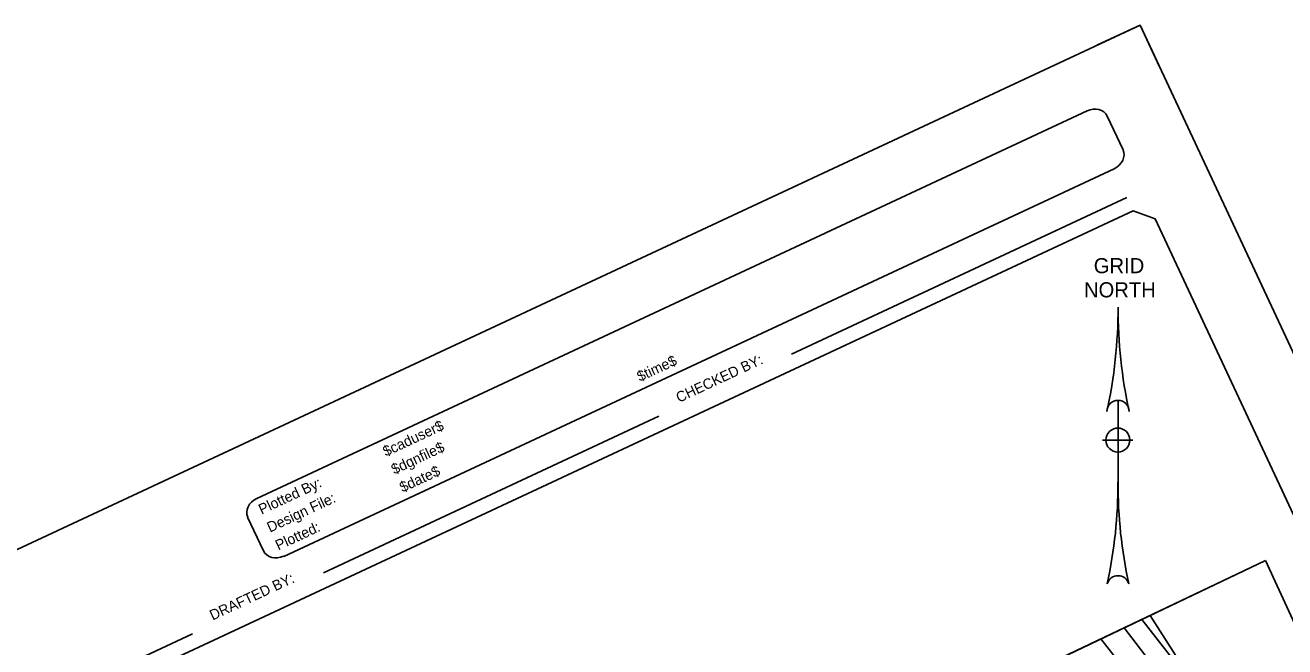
# Model space of a CAD drawing. Extents: x 1040567 to 1041254, y 1126791 to 1127594.
# Drawn here: x 1040797.5 to 1040987.8, y 1127499.7 to 1127593.6 of the extents above; entities that cross this region are included whole.
import ezdxf

# ---------------------------------------------------------------- set-up
doc = ezdxf.new("R2010")
doc.units = 0
for name, color, linetype in [('clip boundary', 7, 'Continuous'), ('DELB', 7, 'Continuous'), ('MHB', 7, 'Continuous'), ('NBS_P', 7, 'Continuous'), ('NBS_P_T', 7, 'Continuous'), ('NML_P', 7, 'Continuous'), ('NNA_P', 7, 'Continuous'), ('SHEET_BORDER', 7, 'Continuous'), ('SHEET_BORDER_CUT', 7, 'Continuous'), ('SHEET_BORDER_TEXT', 7, 'Continuous')]:
    doc.layers.add(name, color=color, linetype=linetype)

msp = doc.modelspace()

# ---------------------------------------------------------------- linework, layer by layer
at = {"layer": 'clip boundary'}
for points in [[(1040965.89, 1127593.65), (1041253.68, 1126977.55), (1040855.03, 1126791.33), (1040567.24, 1127407.43)], [(1040984.84, 1127512.73), (1041214.88, 1127013.05), (1040933.62, 1126879.17), (1040829.04, 1127018.95), (1040710.75, 1127268.88), (1040738.34, 1127281.77), (1040695.57, 1127374.92)]]:
    msp.add_lwpolyline(points, close=True, dxfattribs=at)
at = {"layer": 'DELB'}
for points in [[(1041058.7, 1127320.42), (1041045.83, 1127357.25), (1041019.86, 1127415.53), (1040987.53, 1127471.18), (1040963.49, 1127502.56)], [(1041061.69, 1127320.35), (1041047.64, 1127357.94), (1041023.1, 1127415.85), (1040990.27, 1127472.94), (1040966.17, 1127503.84)], [(1040959.96, 1127500.88), (1040984.81, 1127469.12), (1041015.12, 1127422.04), (1041038.53, 1127369.64), (1041050.29, 1127335.97), (1041054.5, 1127318.26)]]:
    msp.add_lwpolyline(points, dxfattribs=at)
at = {"layer": 'MHB'}
msp.add_lwpolyline([(1040967.39, 1127504.42), (1041043.62, 1127385.06)], dxfattribs=at)
at = {"layer": 'NBS_P'}
for p, q in [((1040957.88, 1127580.71), (1040832.44, 1127522.11)), ((1040963.31, 1127574.79), (1040960.92, 1127579.92)), ((1040836.53, 1127513.35), (1040961.97, 1127571.95)), ((1040831.07, 1127519.27), (1040833.45, 1127514.18))]:
    msp.add_line(p, q, dxfattribs=at)
for centre, major_axis, start_param, end_param in [((1040958.72, 1127578.9), (2.19, 1.02), 0, 1.570796), ((1040961.12, 1127573.76), (2.19, 1.02), 4.712389, 6.283185), ((1040833.28, 1127520.3), (-2.19, -1.02), 4.712389, 6.283185), ((1040835.66, 1127515.21), (-2.19, -1.02), 0, 1.570796)]:
    msp.add_ellipse(centre, major_axis=major_axis, ratio=0.825959, start_param=start_param, end_param=end_param, dxfattribs=at)
at = {"layer": 'NML_P'}
msp.add_line((1040710.81, 1127382.18), (1040984.84, 1127512.73), dxfattribs=at)
at = {"layer": 'NNA_P'}
for p, q in [((1040962.56, 1127524.57), (1040962.56, 1127536.94)), ((1040960.23, 1127530.92), (1040964.77, 1127530.92))]:
    msp.add_line(p, q, dxfattribs=at)
msp.add_circle((1040962.54, 1127530.94), 1.81, dxfattribs=at)
for centre, radius, start, end in [((1040889.47, 1127550.88), 73.09, 347.6515, 0.1139), ((1041035.65, 1127550.88), 73.09, 179.8844, 192.3468), ((1040962.56, 1127535.25), 1.69, 359.9991, 179.9991), ((1040889.47, 1127524.55), 73.09, 347.8917, 0.0159), ((1041035.64, 1127524.55), 73.09, 179.9824, 192.1066), ((1040962.56, 1127508.75), 1.69, 15.894, 164.1052)]:
    msp.add_arc(centre, radius, start, end, dxfattribs=at)
at = {"layer": 'SHEET_BORDER'}
for p, q in [((1040913.25, 1127543.93), (1040963.91, 1127567.6)), ((1040842.53, 1127510.89), (1040893.19, 1127534.56)), ((1040772.08, 1127477.98), (1040822.74, 1127501.65))]:
    msp.add_line(p, q, dxfattribs=at)
msp.add_lwpolyline([(1040856.06, 1126819.41), (1040852.74, 1126820.61), (1040588.22, 1127386.88), (1040589.43, 1127390.2), (1040964.86, 1127565.58), (1040968.18, 1127564.37), (1041232.7, 1126998.11), (1041231.49, 1126994.78)], close=True, dxfattribs=at)
at = {"layer": 'SHEET_BORDER_CUT'}
msp.add_lwpolyline([(1040567.24, 1127407.43), (1040855.03, 1126791.33), (1041253.68, 1126977.55), (1040965.89, 1127593.65)], close=True, dxfattribs=at)
msp.add_lwpolyline([(1040959.48, 1127590.66), (1040965.89, 1127593.65), (1040968.88, 1127587.24)], dxfattribs=at)

# ---------------------------------------------------------------- texts
at = {"layer": 'NBS_P_T'}
for s, height, p in [('$time$', 1.576, (1040890.34, 1127539.73)), ('$caduser$', 1.576, (1040851.95, 1127528.41)), ('$dgnfile$', 1.576, (1040853.22, 1127525.7)), ('$date$', 1.576, (1040854.48, 1127522.99)), ('Plotted By:', 1.5759, (1040833.17, 1127519.64)), ('Design File:', 1.5759, (1040834.44, 1127516.93)), ('Plotted:', 1.576, (1040835.71, 1127514.22))]:
    msp.add_text(s, height=height, rotation=25.0392, dxfattribs=at).set_placement(p)
at = {"layer": 'NNA_P'}
for s, p in [('GRID', (1040958.89, 1127556.16)), ('NORTH', (1040957.41, 1127552.51))]:
    msp.add_text(s, height=2.283, rotation=359.9991, dxfattribs=at).set_placement(p)
at = {"layer": 'SHEET_BORDER_TEXT'}
for s, p in [('CHECKED BY:', (1040896.24, 1127536.56)), ('DRAFTED BY:', (1040825.78, 1127503.65))]:
    msp.add_text(s, height=1.5625, rotation=25.0387, dxfattribs=at).set_placement(p)

doc.saveas('drawing.dxf')
